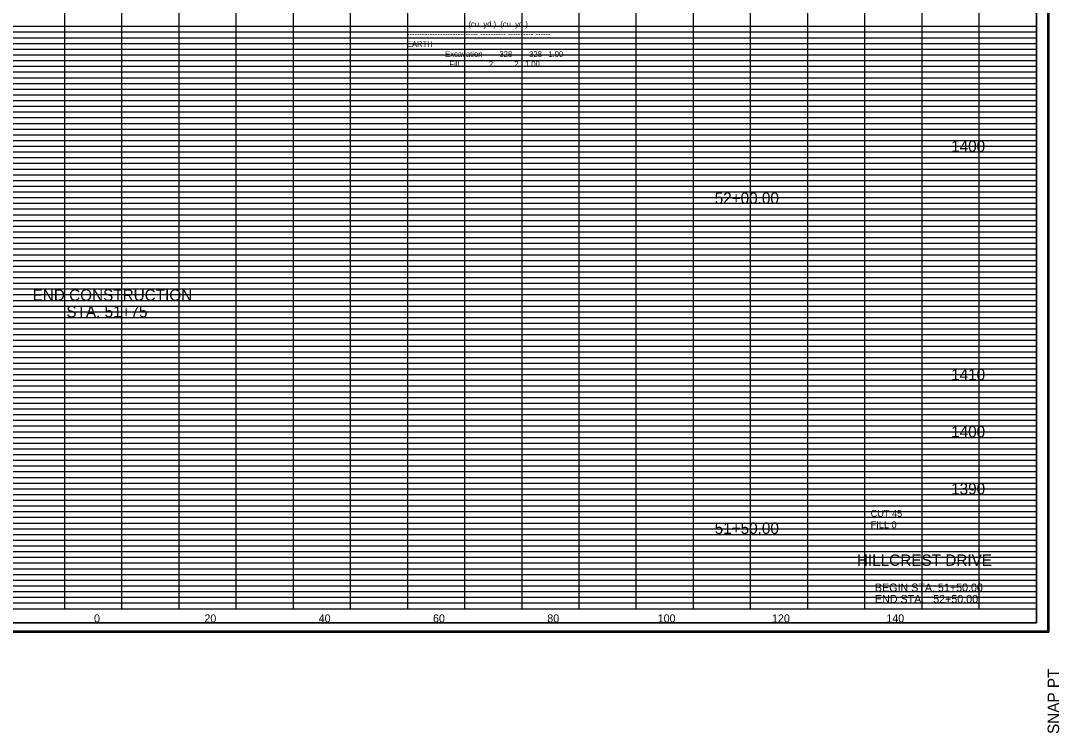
# Model space of a CAD drawing. Extents: x 980 to 1324, y 978 to 1497.
# Drawn here: x 1142.3 to 1324, y 1248.2 to 1373 of the extents above; entities that cross this region are included whole.
import ezdxf

# ---------------------------------------------------------------- set-up
doc = ezdxf.new("R2010")
doc.units = 0
for name, color, linetype in [('DESIGN - SHEET - Corner Text', 7, 'Continuous'), ('DESIGN - SHEET - Light Grid', 7, 'Continuous'), ('DESIGN - SHEET - Linework', 7, 'Continuous'), ('DESIGN - SHEET - Plot Shape', 7, 'Continuous'), ('DESIGN - TYPICAL - Text', 7, 'Continuous')]:
    doc.layers.add(name, color=color, linetype=linetype)

# ---------------------------------------------------------------- blocks, each defined once
blk = doc.blocks.new('XSTSHT')
at = {"layer": 'DESIGN - SHEET - Light Grid'}
for p, q in [((8, 10.2), (16, 10.2)), ((16, 10.2), (24, 10.2)), ((24, 10.2), (32, 10.2)), ((8, 10.1), (16, 10.1)), ((16, 10.1), (24, 10.1)), ((24, 10.1), (32, 10.1)), ((8, 9.9), (16, 9.9)), ((16, 9.9), (24, 9.9)), ((24, 9.9), (32, 9.9)), ((8, 9.8), (16, 9.8)), ((8, 9.7), (16, 9.7)), ((16, 9.8), (24, 9.8)), ((16, 9.7), (24, 9.7)), ((24, 9.8), (32, 9.8)), ((24, 9.7), (32, 9.7)), ((8, 9.6), (16, 9.6)), ((8, 9.5), (16, 9.5)), ((16, 9.6), (24, 9.6)), ((16, 9.5), (24, 9.5)), ((24, 9.6), (32, 9.6)), ((24, 9.5), (32, 9.5)), ((8, 9.4), (16, 9.4)), ((8, 9.3), (16, 9.3)), ((16, 9.4), (24, 9.4)), ((16, 9.3), (24, 9.3)), ((24, 9.4), (32, 9.4)), ((24, 9.3), (32, 9.3)), ((8, 9.2), (16, 9.2)), ((8, 9.1), (16, 9.1)), ((16, 9.2), (24, 9.2)), ((16, 9.1), (24, 9.1)), ((24, 9.2), (32, 9.2)), ((24, 9.1), (32, 9.1)), ((8, 8.9), (16, 8.9)), ((8, 8.8), (16, 8.8)), ((16, 8.9), (24, 8.9)), ((16, 8.8), (24, 8.8)), ((24, 8.9), (32, 8.9)), ((24, 8.8), (32, 8.8)), ((8, 8.7), (16, 8.7)), ((8, 8.6), (16, 8.6)), ((16, 8.7), (24, 8.7)), ((16, 8.6), (24, 8.6)), ((24, 8.7), (32, 8.7)), ((24, 8.6), (32, 8.6)), ((8, 8.5), (16, 8.5)), ((8, 8.4), (16, 8.4)), ((16, 8.5), (24, 8.5)), ((16, 8.4), (24, 8.4)), ((24, 8.5), (32, 8.5)), ((24, 8.4), (32, 8.4)), ((8, 8.3), (16, 8.3)), ((8, 8.2), (16, 8.2)), ((16, 8.3), (24, 8.3)), ((16, 8.2), (24, 8.2)), ((24, 8.3), (32, 8.3)), ((24, 8.2), (32, 8.2)), ((8, 8.1), (16, 8.1)), ((16, 8.1), (24, 8.1)), ((24, 8.1), (32, 8.1)), ((8, 7.9), (16, 7.9)), ((16, 7.9), (24, 7.9)), ((24, 7.9), (32, 7.9)), ((8, 7.8), (16, 7.8)), ((8, 7.7), (16, 7.7)), ((16, 7.8), (24, 7.8)), ((16, 7.7), (24, 7.7)), ((24, 7.8), (32, 7.8)), ((24, 7.7), (32, 7.7)), ((8, 7.6), (16, 7.6)), ((8, 7.5), (16, 7.5)), ((16, 7.6), (24, 7.6)), ((16, 7.5), (24, 7.5)), ((24, 7.6), (32, 7.6)), ((24, 7.5), (32, 7.5)), ((8, 7.4), (16, 7.4)), ((8, 7.3), (16, 7.3)), ((16, 7.4), (24, 7.4)), ((16, 7.3), (24, 7.3)), ((24, 7.4), (32, 7.4)), ((24, 7.3), (32, 7.3)), ((8, 7.2), (16, 7.2)), ((8, 7.1), (16, 7.1)), ((16, 7.2), (24, 7.2)), ((16, 7.1), (24, 7.1)), ((24, 7.2), (32, 7.2)), ((24, 7.1), (32, 7.1)), ((8, 6.9), (16, 6.9)), ((8, 6.8), (16, 6.8)), ((16, 6.9), (24, 6.9)), ((16, 6.8), (24, 6.8)), ((24, 6.9), (32, 6.9)), ((24, 6.8), (32, 6.8)), ((8, 6.7), (16, 6.7)), ((8, 6.6), (16, 6.6)), ((16, 6.7), (24, 6.7)), ((16, 6.6), (24, 6.6)), ((24, 6.7), (32, 6.7)), ((24, 6.6), (32, 6.6)), ((8, 6.5), (16, 6.5)), ((8, 6.4), (16, 6.4)), ((16, 6.5), (24, 6.5)), ((16, 6.4), (24, 6.4)), ((24, 6.5), (32, 6.5)), ((24, 6.4), (32, 6.4)), ((8, 6.3), (16, 6.3)), ((8, 6.2), (16, 6.2)), ((16, 6.3), (24, 6.3)), ((16, 6.2), (24, 6.2)), ((24, 6.3), (32, 6.3)), ((24, 6.2), (32, 6.2)), ((8, 6.1), (16, 6.1)), ((16, 6.1), (24, 6.1)), ((24, 6.1), (32, 6.1)), ((8, 5.9), (16, 5.9)), ((16, 5.9), (24, 5.9)), ((24, 5.9), (32, 5.9)), ((8, 5.8), (16, 5.8)), ((8, 5.7), (16, 5.7)), ((16, 5.8), (24, 5.8)), ((16, 5.7), (24, 5.7)), ((24, 5.8), (32, 5.8)), ((24, 5.7), (32, 5.7)), ((8, 5.6), (16, 5.6)), ((8, 5.5), (16, 5.5)), ((16, 5.6), (24, 5.6)), ((16, 5.5), (24, 5.5)), ((24, 5.6), (32, 5.6)), ((24, 5.5), (32, 5.5)), ((8, 5.4), (16, 5.4)), ((8, 5.3), (16, 5.3)), ((16, 5.4), (24, 5.4)), ((16, 5.3), (24, 5.3)), ((24, 5.4), (32, 5.4)), ((24, 5.3), (32, 5.3)), ((8, 5.2), (16, 5.2)), ((8, 5.1), (16, 5.1)), ((16, 5.2), (24, 5.2)), ((16, 5.1), (24, 5.1)), ((24, 5.2), (32, 5.2)), ((24, 5.1), (32, 5.1)), ((8, 4.9), (16, 4.9)), ((8, 4.8), (16, 4.8)), ((16, 4.9), (24, 4.9)), ((16, 4.8), (24, 4.8)), ((24, 4.9), (32, 4.9)), ((24, 4.8), (32, 4.8)), ((8, 4.7), (16, 4.7)), ((8, 4.6), (16, 4.6)), ((16, 4.7), (24, 4.7)), ((16, 4.6), (24, 4.6)), ((24, 4.7), (32, 4.7)), ((24, 4.6), (32, 4.6)), ((8, 4.5), (16, 4.5)), ((8, 4.4), (16, 4.4)), ((16, 4.5), (24, 4.5)), ((16, 4.4), (24, 4.4)), ((24, 4.5), (32, 4.5)), ((24, 4.4), (32, 4.4)), ((8, 4.3), (16, 4.3)), ((8, 4.2), (16, 4.2)), ((16, 4.3), (24, 4.3)), ((16, 4.2), (24, 4.2)), ((24, 4.3), (32, 4.3)), ((24, 4.2), (32, 4.2)), ((8, 4.1), (16, 4.1)), ((16, 4.1), (24, 4.1)), ((24, 4.1), (32, 4.1)), ((8, 3.9), (16, 3.9)), ((16, 3.9), (24, 3.9)), ((24, 3.9), (32, 3.9)), ((8, 3.8), (16, 3.8)), ((8, 3.7), (16, 3.7)), ((16, 3.8), (24, 3.8)), ((16, 3.7), (24, 3.7)), ((24, 3.8), (32, 3.8)), ((24, 3.7), (32, 3.7)), ((8, 3.6), (16, 3.6)), ((8, 3.5), (16, 3.5)), ((16, 3.6), (24, 3.6)), ((16, 3.5), (24, 3.5)), ((24, 3.6), (32, 3.6)), ((24, 3.5), (32, 3.5)), ((8, 3.4), (16, 3.4)), ((8, 3.3), (16, 3.3)), ((16, 3.4), (24, 3.4)), ((16, 3.3), (24, 3.3)), ((24, 3.4), (32, 3.4)), ((24, 3.3), (32, 3.3)), ((8, 3.2), (16, 3.2)), ((8, 3.1), (16, 3.1)), ((16, 3.2), (24, 3.2)), ((16, 3.1), (24, 3.1)), ((24, 3.2), (32, 3.2)), ((24, 3.1), (32, 3.1)), ((8, 2.9), (16, 2.9)), ((8, 2.8), (16, 2.8)), ((16, 2.9), (24, 2.9)), ((16, 2.8), (24, 2.8)), ((24, 2.9), (32, 2.9)), ((24, 2.8), (32, 2.8)), ((8, 2.7), (16, 2.7)), ((8, 2.6), (16, 2.6)), ((16, 2.7), (24, 2.7)), ((16, 2.6), (24, 2.6)), ((24, 2.7), (32, 2.7)), ((24, 2.6), (32, 2.6)), ((8, 2.5), (16, 2.5)), ((8, 2.4), (16, 2.4)), ((16, 2.5), (24, 2.5)), ((16, 2.4), (24, 2.4)), ((24, 2.5), (32, 2.5)), ((24, 2.4), (32, 2.4)), ((8, 2.3), (16, 2.3)), ((8, 2.2), (16, 2.2)), ((16, 2.3), (24, 2.3)), ((16, 2.2), (24, 2.2)), ((24, 2.3), (32, 2.3)), ((24, 2.2), (32, 2.2)), ((8, 2.1), (16, 2.1)), ((16, 2.1), (24, 2.1)), ((24, 2.1), (32, 2.1)), ((8, 1.9), (16, 1.9)), ((16, 1.9), (24, 1.9)), ((24, 1.9), (32, 1.9)), ((8, 1.8), (16, 1.8)), ((8, 1.7), (16, 1.7)), ((16, 1.8), (24, 1.8)), ((16, 1.7), (24, 1.7)), ((24, 1.8), (32, 1.8)), ((24, 1.7), (32, 1.7)), ((8, 1.6), (16, 1.6)), ((8, 1.5), (16, 1.5)), ((16, 1.6), (24, 1.6)), ((16, 1.5), (24, 1.5)), ((24, 1.6), (32, 1.6)), ((24, 1.5), (32, 1.5)), ((8, 1.4), (16, 1.4)), ((8, 1.3), (16, 1.3)), ((16, 1.4), (24, 1.4)), ((16, 1.3), (24, 1.3)), ((24, 1.4), (32, 1.4)), ((24, 1.3), (32, 1.3)), ((8, 1.2), (16, 1.2)), ((8, 1.1), (16, 1.1)), ((16, 1.2), (24, 1.2)), ((16, 1.1), (24, 1.1)), ((24, 1.2), (32, 1.2)), ((24, 1.1), (32, 1.1)), ((8, 0.9), (16, 0.9)), ((8, 0.8), (16, 0.8)), ((16, 0.9), (24, 0.9)), ((16, 0.8), (24, 0.8)), ((24, 0.9), (32, 0.9)), ((24, 0.8), (32, 0.8)), ((8, 0.7), (16, 0.7)), ((8, 0.6), (16, 0.6)), ((16, 0.7), (24, 0.7)), ((16, 0.6), (24, 0.6)), ((24, 0.7), (32, 0.7)), ((24, 0.6), (32, 0.6)), ((8, 0.5), (16, 0.5)), ((8, 0.4), (16, 0.4)), ((16, 0.5), (24, 0.5)), ((16, 0.4), (24, 0.4)), ((24, 0.5), (32, 0.5)), ((24, 0.4), (32, 0.4)), ((8, 0.3), (16, 0.3)), ((8, 0.2), (16, 0.2)), ((16, 0.3), (24, 0.3)), ((16, 0.2), (24, 0.2)), ((24, 0.3), (32, 0.3)), ((24, 0.2), (32, 0.2)), ((8, 0.1), (16, 0.1)), ((16, 0.1), (24, 0.1)), ((24, 0.1), (32, 0.1))]:
    blk.add_line(p, q, dxfattribs=at)
at = {"layer": 'DESIGN - SHEET - Linework'}
for p, q in [((32.217, 21.414), (32.217, -0.414)), ((15, 0), (15, 21)), ((16, 0), (16, 21)), ((17, 0), (17, 21)), ((18, 0), (18, 21)), ((19, 0), (19, 21)), ((20, 0), (20, 21)), ((21, 0), (21, 21)), ((22, 0), (22, 21)), ((23, 0), (23, 21)), ((24, 0), (24, 21)), ((25, 0), (25, 21)), ((26, 0), (26, 21)), ((27, 0), (27, 21)), ((28, 0), (28, 20)), ((29, 0), (29, 20)), ((30, 0), (30, 20)), ((31, 0), (31, 20)), ((0, 10), (32, 10)), ((0, 9), (32, 9)), ((0, 8), (32, 8)), ((0, 7), (32, 7)), ((0, 6), (32, 6)), ((0, 5), (32, 5)), ((0, 4), (32, 4)), ((0, 3), (32, 3)), ((0, 2), (32, 2)), ((0, 1), (32, 1)), ((-1.823, -0.414), (32.217, -0.414))]:
    blk.add_line(p, q, dxfattribs=at)
blk.add_lwpolyline([(0, 21), (0, 0), (32, 0), (32, 21), (0, 21)], dxfattribs=at)
at = {"layer": 'DESIGN - SHEET - Plot Shape'}
for points in [[(-1.803, 21.394), (32.197, 21.394), (32.197, -0.394), (-1.803, -0.394)], [(-0.85, 21), (32, 21), (32, -0.25), (-0.85, -0.25)]]:
    blk.add_lwpolyline(points, close=True, dxfattribs=at)
at = {"layer": 'DESIGN - SHEET - Corner Text'}
blk.add_text('SNAP PT  ', height=0.2, rotation=90, dxfattribs=at).set_placement((32.397, -2.194))

msp = doc.modelspace()

# ---------------------------------------------------------------- linework, layer by layer
at = {"layer": 'DESIGN - SHEET - Plot Shape'}
msp.add_lwpolyline([(991.5, 1267.5), (1320, 1267.5), (1320, 1480), (991.5, 1480)], close=True, dxfattribs=at)

# ---------------------------------------------------------------- block references
at = {"layer": 'DESIGN - TYPICAL - Text', "xscale": 10, "yscale": 10}
msp.add_blockref('XSTSHT', (1000, 1270), dxfattribs=at)

# ---------------------------------------------------------------- texts
at = {"layer": 'DESIGN - SHEET - Corner Text'}
for s, height, p in [('HILLCREST DRIVE', 2, (1288.6, 1277.5)), ('BEGIN STA. 51+50.00', 1.4, (1291.75, 1273)), ('END STA.   52+50.00', 1.4, (1291.75, 1271))]:
    msp.add_text(s, height=height, dxfattribs=at).set_placement(p)
at = {"layer": 'DESIGN - TYPICAL - Text'}
for s, height, p in [('                                     (cu. yd.)  (cu. yd.)', 1, (1206.88, 1371.89)), ('        ---------------------------- ---------- ---------- ------', 1, (1206.88, 1370.14)), ('        EARTH', 1, (1206.88, 1368.39)), ('                          Excavation        328        328   1.00', 1, (1206.88, 1366.64)), ('                            Fill              2          2   1.00', 1, (1206.88, 1364.89)), ('     1400     ', 2, (1301.37, 1350)), ('     52+00.00     ', 2, (1260, 1340.91)), ('END CONSTRUCTION', 2, (1144.36, 1323.93)), ('STA. 51+75', 2, (1150.27, 1321.03)), ('     1410     ', 2, (1301.37, 1310)), ('     1400     ', 2, (1301.37, 1300)), ('     1390     ', 2, (1301.37, 1290)), ('CUT 45', 1.2, (1291, 1286.09)), ('     51+50.00     ', 2, (1260, 1283.09)), ('FILL 0', 1.2, (1291, 1284.09)), ('     0     ', 1.4, (1152.51, 1267.6)), ('     0     ', 1.4, (1152.51, 1267.6)), ('     20     ', 1.4, (1171.82, 1267.6)), ('     40     ', 1.4, (1191.82, 1267.6)), ('     60     ', 1.4, (1211.82, 1267.6)), ('     80     ', 1.4, (1231.82, 1267.6)), ('     100     ', 1.4, (1251.14, 1267.6)), ('     120     ', 1.4, (1271.14, 1267.6)), ('     140     ', 1.4, (1291.14, 1267.6))]:
    msp.add_text(s, height=height, dxfattribs=at).set_placement(p)

doc.saveas('drawing.dxf')
